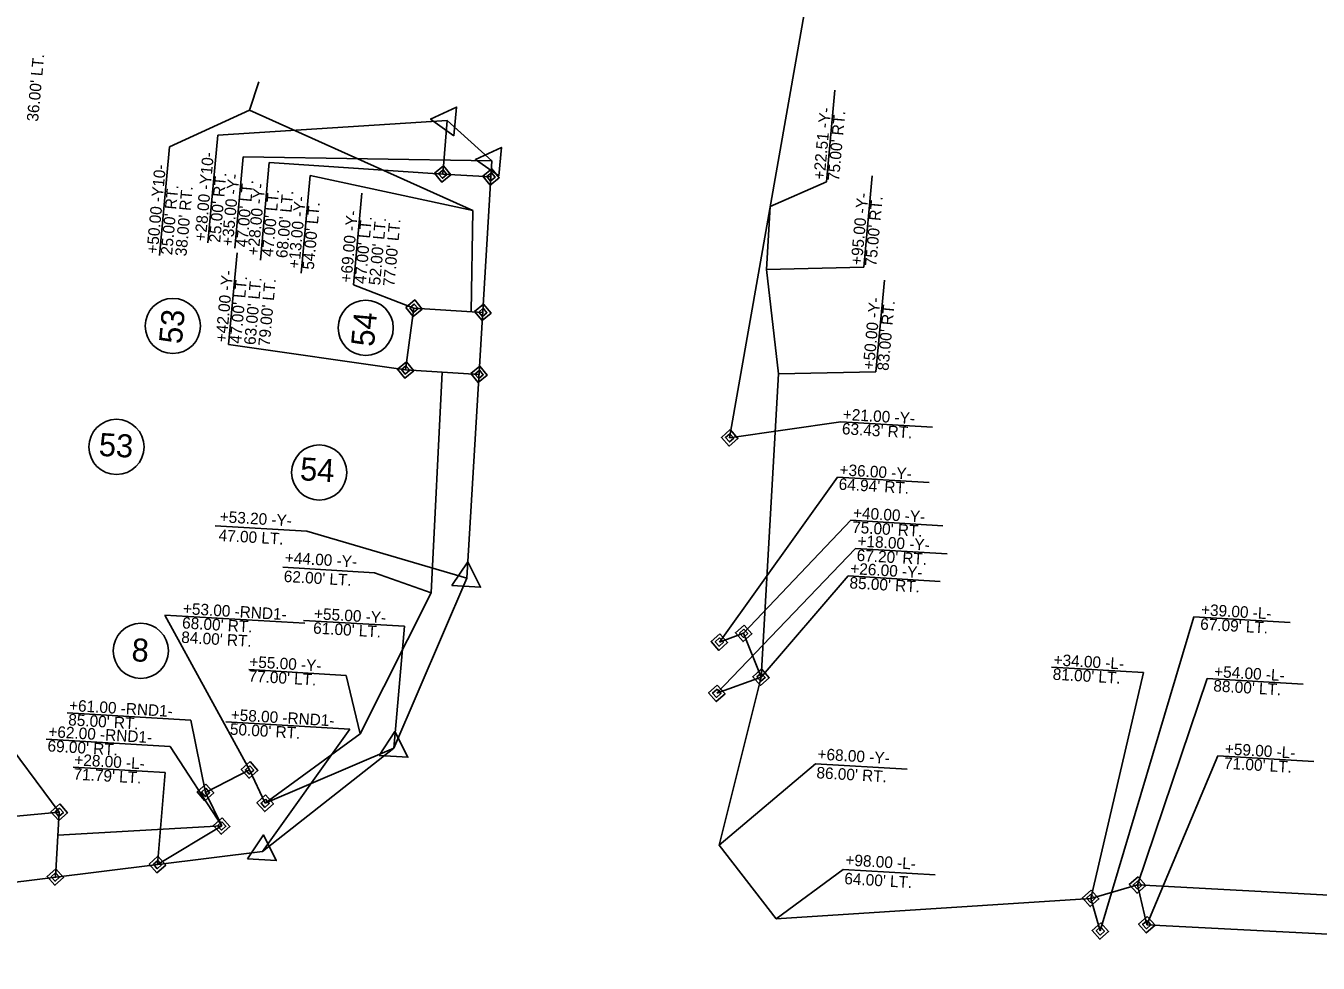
# Model space of a CAD drawing. Extents: x 2010883 to 2014849, y 442000 to 447413.
# Drawn here: x 2011813 to 2012375, y 445024 to 445432 of the extents above; entities that cross this region are included whole.
import ezdxf

# ---------------------------------------------------------------- set-up
doc = ezdxf.new("R2010")
doc.units = 0
for name, color, linetype in [('Prop Easement Construction', 7, 'Continuous'), ('Prop Easement Construction Station Offsets', 7, 'Continuous'), ('Prop Easement Permanent Drainage', 7, 'Continuous'), ('Prop Easement Permanent Drainage Station Offsets', 7, 'Continuous'), ('Prop Easement Permanent Utility', 7, 'Continuous'), ('Prop Easement Permanent Utility Station Offsets', 7, 'Continuous'), ('Prop Parcel Number CELL', 7, 'Continuous'), ('Prop Parcel Number Text', 7, 'Continuous'), ('Prop ROW Marker CELL', 7, 'Continuous'), ('Prop ROW Permanent Easement CELL', 7, 'Continuous'), ('Prop ROW RW Lines', 7, 'Continuous'), ('Prop ROW Station Offsets', 7, 'Continuous')]:
    doc.layers.add(name, color=color, linetype=linetype)

msp = doc.modelspace()

# ---------------------------------------------------------------- linework, layer by layer
at = {"layer": 'Prop Easement Construction'}
for p, q in [((2011910.56, 445395.34), (2011914.63, 445407.68)), ((2012007.68, 445351.78), (2011910.56, 445395.34)), ((2012007.03, 445307.74), (2012007.68, 445351.78)), ((2012135.36, 445326.06), (2012137.01, 445353.51)), ((2012140.64, 445280.66), (2012135.36, 445326.06)), ((2011989.53, 445185.57), (2011994.41, 445281.45)), ((2012133.02, 445148.82), (2012140.64, 445280.66)), ((2011958.68, 445124.25), (2011989.53, 445185.57)), ((2012114.82, 445075.77), (2012133.02, 445148.82)), ((2011917.38, 445094.01), (2011958.68, 445124.25)), ((2011827.22, 445080.12), (2011898.48, 445084.13)), ((2012114.82, 445075.77), (2012139.62, 445043.68)), ((2012296.76, 445058.46), (2012623.31, 445041.21)), ((2012139.62, 445043.68), (2012276.39, 445052.65))]:
    msp.add_line(p, q, dxfattribs=at)
at = {"layer": 'Prop Easement Construction Station Offsets'}
for p, q in [((2012161.48, 445364.18), (2012165.14, 445404.01)), ((2011910.56, 445395.34), (2011875.84, 445379.49)), ((2011871.49, 445332.23), (2011875.84, 445379.49)), ((2011933.03, 445324.52), (2011936.93, 445366.95)), ((2011936.93, 445366.95), (2012007.68, 445351.78)), ((2012177.71, 445327.06), (2012181.37, 445366.89)), ((2012137.01, 445353.51), (2012161.48, 445364.18)), ((2012135.36, 445326.06), (2012177.71, 445327.06)), ((2012182.99, 445281.66), (2012186.65, 445321.49)), ((2012140.64, 445280.66), (2012182.99, 445281.66)), ((2011925, 445196.59), (2011964.94, 445194.23)), ((2011989.53, 445185.57), (2011964.94, 445194.23)), ((2011910.32, 445152.12), (2011952.66, 445149.62)), ((2011958.68, 445124.25), (2011952.66, 445149.62)), ((2012114.82, 445075.77), (2012156.64, 445111.2)), ((2012156.64, 445111.2), (2012196.57, 445108.85)), ((2012139.62, 445043.68), (2012168.77, 445065.18)), ((2012168.77, 445065.18), (2012208.7, 445062.82))]:
    msp.add_line(p, q, dxfattribs=at)
at = {"layer": 'Prop Easement Permanent Drainage'}
for p, q in [((2011994.6, 445367.59), (2011996.46, 445390.81)), ((2012015.56, 445366.33), (2011994.6, 445367.59)), ((2011807.67, 445088.29), (2011827.81, 445090.11)), ((2011826.15, 445061.91), (2011827.81, 445090.11))]:
    msp.add_line(p, q, dxfattribs=at)
at = {"layer": 'Prop Easement Permanent Drainage Station Offsets'}
for p, q in [((2011915.28, 445330.14), (2011919.18, 445372.58)), ((2011919.18, 445372.58), (2011994.6, 445367.59)), ((2011793.66, 445136.03), (2011827.81, 445090.11))]:
    msp.add_line(p, q, dxfattribs=at)
at = {"layer": 'Prop Easement Permanent Utility'}
for p, q in [((2012119.36, 445252.89), (2012162.12, 445496.62)), ((2011978.45, 445282.41), (2011982.07, 445309.24)), ((2011982.07, 445309.24), (2012012.02, 445307.44)), ((2012010.39, 445280.49), (2011978.45, 445282.41)), ((2012125.45, 445167.9), (2012114.88, 445164.09)), ((2012133.02, 445148.82), (2012125.45, 445167.9)), ((2012113.76, 445141.83), (2012133.02, 445148.82)), ((2011917.38, 445094.01), (2011973.39, 445117.95)), ((2011891.43, 445098.71), (2011910.59, 445108.5)), ((2011910.59, 445108.5), (2011917.38, 445094.01)), ((2011898.48, 445084.13), (2011891.43, 445098.71)), ((2011870.55, 445067.34), (2011898.48, 445084.13)), ((2012276.39, 445052.65), (2012296.76, 445058.46)), ((2012296.76, 445058.46), (2012300.75, 445041.19)), ((2012280.56, 445038.46), (2012276.39, 445052.65)), ((2012300.75, 445041.19), (2012618.32, 445024.48))]:
    msp.add_line(p, q, dxfattribs=at)
at = {"layer": 'Prop Easement Permanent Utility Station Offsets'}
for p, q in [((2011955.74, 445319.43), (2011959.4, 445359.26)), ((2011901.5, 445293.47), (2011905.17, 445333.3)), ((2011955.74, 445319.43), (2011982.07, 445309.24)), ((2011901.5, 445293.47), (2011978.45, 445282.41)), ((2012119.36, 445252.89), (2012167.68, 445259.86)), ((2012167.68, 445259.86), (2012207.61, 445257.5)), ((2012114.88, 445164.09), (2012166.26, 445235.76)), ((2012166.26, 445235.76), (2012206.19, 445233.41)), ((2012125.45, 445167.9), (2012172.12, 445217.03)), ((2012172.12, 445217.03), (2012212.06, 445214.68)), ((2012113.76, 445141.83), (2012174.09, 445204.81)), ((2012174.09, 445204.81), (2012214.02, 445202.46)), ((2012133.02, 445148.82), (2012170.96, 445192.84)), ((2012170.96, 445192.84), (2012210.89, 445190.48)), ((2011873.68, 445175.84), (2011934.64, 445172.24)), ((2011910.59, 445108.5), (2011873.68, 445175.84)), ((2012280.56, 445038.46), (2012321.26, 445175.12)), ((2012321.26, 445175.12), (2012363.06, 445172.66)), ((2012259.35, 445153.18), (2012299.28, 445150.83)), ((2012276.39, 445052.65), (2012299.28, 445150.83)), ((2012296.76, 445058.46), (2012326.97, 445148.24)), ((2012326.97, 445148.24), (2012368.77, 445145.78)), ((2011831.21, 445133.29), (2011885.12, 445130.12)), ((2011891.43, 445098.71), (2011885.12, 445130.12)), ((2011822.21, 445121.93), (2011876.12, 445118.75)), ((2011898.48, 445084.13), (2011876.12, 445118.75)), ((2012300.75, 445041.19), (2012331.62, 445114.6)), ((2012331.62, 445114.6), (2012373.42, 445112.13)), ((2011833.91, 445109.71), (2011873.84, 445107.36)), ((2011870.55, 445067.34), (2011873.84, 445107.36))]:
    msp.add_line(p, q, dxfattribs=at)
at = {"layer": 'Prop Parcel Number CELL'}
for p, q in [((2011877.23, 445301.55), (2011877.23, 445301.55)), ((2011961.1, 445300.73), (2011961.1, 445300.73)), ((2011852.71, 445248.95), (2011852.71, 445248.95)), ((2011940.89, 445237.82), (2011940.89, 445237.82)), ((2011863.3, 445160.26), (2011863.3, 445160.26))]:
    msp.add_line(p, q, dxfattribs=at)
for centre in [(2011877.23, 445301.55), (2011961.1, 445300.73), (2011852.71, 445248.95), (2011940.89, 445237.82), (2011863.3, 445160.26)]:
    msp.add_circle(centre, 12, dxfattribs=at)
at = {"layer": 'Prop ROW Marker CELL'}
for p, q in [((2011996.46, 445390.81), (2011996.46, 445390.81)), ((2012015.99, 445373.32), (2012015.99, 445373.32)), ((2011994.6, 445367.59), (2011994.6, 445367.59)), ((2012015.56, 445366.33), (2012015.56, 445366.33)), ((2011982.07, 445309.24), (2011982.07, 445309.24)), ((2012012.02, 445307.44), (2012012.02, 445307.44)), ((2011978.45, 445282.41), (2011978.45, 445282.41)), ((2012010.39, 445280.49), (2012010.39, 445280.49)), ((2012119.36, 445252.89), (2012119.36, 445252.89)), ((2012005.06, 445191.85), (2012005.06, 445191.85)), ((2012114.88, 445164.09), (2012114.88, 445164.09)), ((2012125.45, 445167.9), (2012125.45, 445167.9)), ((2012133.02, 445148.82), (2012133.02, 445148.82)), ((2012113.76, 445141.83), (2012113.76, 445141.83)), ((2011973.39, 445117.95), (2011973.39, 445117.95)), ((2011910.59, 445108.5), (2011910.59, 445108.5)), ((2011891.43, 445098.71), (2011891.43, 445098.71)), ((2011917.38, 445094.01), (2011917.38, 445094.01)), ((2011827.81, 445090.11), (2011827.81, 445090.11)), ((2011898.48, 445084.13), (2011898.48, 445084.13)), ((2011916.2, 445073.02), (2011916.2, 445073.02)), ((2011870.55, 445067.34), (2011870.55, 445067.34)), ((2011826.15, 445061.91), (2011826.15, 445061.91)), ((2012296.76, 445058.46), (2012296.76, 445058.46)), ((2012276.39, 445052.65), (2012276.39, 445052.65)), ((2012300.75, 445041.19), (2012300.75, 445041.19)), ((2012280.56, 445038.46), (2012280.56, 445038.46))]:
    msp.add_line(p, q, dxfattribs=at)
for points in [[(2011999.48, 445384.25), (2011989.29, 445391.47), (2012000.62, 445396.7)], [(2012019, 445366.77), (2012008.82, 445373.98), (2012020.14, 445379.21)], [(2011998.6, 445188.62), (2012005.48, 445199.04), (2012011.08, 445187.89)], [(2011966.94, 445114.73), (2011973.81, 445125.14), (2011979.42, 445113.99)], [(2011909.74, 445069.79), (2011916.62, 445080.21), (2011922.22, 445069.06)]]:
    msp.add_lwpolyline(points, close=True, dxfattribs=at)
at = {"layer": 'Prop ROW Permanent Easement CELL'}
for points in [[(2011991.02, 445367.92), (2011994.93, 445371.18), (2011998.19, 445367.26), (2011994.27, 445364.01)], [(2011992.81, 445367.76), (2011994.77, 445369.39), (2011996.39, 445367.43), (2011994.44, 445365.8)], [(2012011.98, 445366.66), (2012015.89, 445369.92), (2012019.15, 445366), (2012015.24, 445362.75)], [(2012013.77, 445366.5), (2012015.73, 445368.12), (2012017.36, 445366.17), (2012015.4, 445364.54)], [(2011978.49, 445309.57), (2011982.4, 445312.83), (2011985.66, 445308.91), (2011981.74, 445305.66)], [(2011980.28, 445309.41), (2011982.24, 445311.03), (2011983.86, 445309.08), (2011981.91, 445307.45)], [(2012008.43, 445307.77), (2012012.35, 445311.02), (2012015.6, 445307.11), (2012011.69, 445303.85)], [(2012010.23, 445307.6), (2012012.18, 445309.23), (2012013.81, 445307.27), (2012011.85, 445305.65)], [(2011974.87, 445282.74), (2011978.78, 445286), (2011982.04, 445282.08), (2011978.12, 445278.83)], [(2011976.66, 445282.58), (2011978.62, 445284.2), (2011980.24, 445282.25), (2011978.29, 445280.62)], [(2012006.81, 445280.82), (2012010.72, 445284.07), (2012013.98, 445280.16), (2012010.07, 445276.9)], [(2012008.6, 445280.65), (2012010.56, 445282.28), (2012012.19, 445280.32), (2012010.23, 445278.69)], [(2012119.57, 445256.48), (2012122.95, 445252.67), (2012119.15, 445249.29), (2012115.77, 445253.1)], [(2012119.47, 445254.68), (2012121.16, 445252.78), (2012119.25, 445251.09), (2012117.56, 445252.99)], [(2012125.66, 445171.49), (2012129.04, 445167.69), (2012125.24, 445164.3), (2012121.85, 445168.11)], [(2012125.55, 445169.69), (2012127.24, 445167.79), (2012125.34, 445166.1), (2012123.65, 445168)], [(2012115.1, 445167.68), (2012118.48, 445163.88), (2012114.67, 445160.49), (2012111.29, 445164.3)], [(2012114.99, 445165.88), (2012116.68, 445163.98), (2012114.78, 445162.29), (2012113.09, 445164.19)], [(2012133.23, 445152.41), (2012136.61, 445148.6), (2012132.8, 445145.22), (2012129.42, 445149.03)], [(2012133.12, 445150.61), (2012134.81, 445148.71), (2012132.91, 445147.02), (2012131.22, 445148.92)], [(2012113.97, 445145.42), (2012117.36, 445141.62), (2012113.55, 445138.24), (2012110.17, 445142.04)], [(2012113.87, 445143.63), (2012115.56, 445141.73), (2012113.66, 445140.03), (2012111.97, 445141.94)], [(2011910.8, 445112.09), (2011914.19, 445108.28), (2011910.38, 445104.9), (2011907, 445108.71)], [(2011910.7, 445110.29), (2011912.39, 445108.39), (2011910.49, 445106.7), (2011908.8, 445108.6)], [(2011891.64, 445102.3), (2011895.02, 445098.5), (2011891.21, 445095.12), (2011887.83, 445098.92)], [(2011891.53, 445100.51), (2011893.22, 445098.6), (2011891.32, 445096.91), (2011889.63, 445098.82)], [(2011917.59, 445097.6), (2011920.98, 445093.8), (2011917.17, 445090.41), (2011913.79, 445094.22)], [(2011828.03, 445093.7), (2011831.41, 445089.9), (2011827.6, 445086.51), (2011824.22, 445090.32)], [(2011827.92, 445091.9), (2011829.61, 445090), (2011827.71, 445088.31), (2011826.02, 445090.21)], [(2011917.49, 445095.8), (2011919.18, 445093.9), (2011917.28, 445092.21), (2011915.59, 445094.11)], [(2011898.7, 445087.72), (2011902.08, 445083.92), (2011898.27, 445080.54), (2011894.89, 445084.34)], [(2011898.59, 445085.93), (2011900.28, 445084.02), (2011898.38, 445082.33), (2011896.69, 445084.24)], [(2011870.76, 445070.94), (2011874.14, 445067.13), (2011870.34, 445063.75), (2011866.95, 445067.55)], [(2011870.65, 445069.14), (2011872.34, 445067.24), (2011870.44, 445065.55), (2011868.75, 445067.45)], [(2011826.36, 445065.51), (2011829.75, 445061.7), (2011825.94, 445058.32), (2011822.56, 445062.13)], [(2011826.26, 445063.71), (2011827.95, 445061.81), (2011826.05, 445060.12), (2011824.35, 445062.02)], [(2012296.98, 445062.05), (2012300.36, 445058.24), (2012296.55, 445054.86), (2012293.17, 445058.67)], [(2012296.87, 445060.25), (2012298.56, 445058.35), (2012296.66, 445056.66), (2012294.97, 445058.56)], [(2012276.6, 445056.24), (2012279.98, 445052.43), (2012276.17, 445049.05), (2012272.79, 445052.86)], [(2012276.49, 445054.44), (2012278.18, 445052.54), (2012276.28, 445050.85), (2012274.59, 445052.75)], [(2012280.77, 445042.06), (2012284.15, 445038.25), (2012280.35, 445034.87), (2012276.96, 445038.67)], [(2012300.97, 445044.79), (2012304.35, 445040.98), (2012300.54, 445037.6), (2012297.16, 445041.4)], [(2012300.86, 445042.99), (2012302.55, 445041.09), (2012300.65, 445039.4), (2012298.96, 445041.3)], [(2012280.66, 445040.26), (2012282.36, 445038.36), (2012280.45, 445036.67), (2012278.76, 445038.57)]]:
    msp.add_lwpolyline(points, close=True, dxfattribs=at)
at = {"layer": 'Prop ROW RW Lines'}
for p, q in [((2012015.99, 445373.32), (2011996.46, 445390.81)), ((2012005.06, 445191.85), (2012015.99, 445373.32)), ((2011973.39, 445117.95), (2012005.06, 445191.85)), ((2011916.2, 445073.02), (2011973.39, 445117.95)), ((2011751.47, 445052.53), (2011916.2, 445073.02))]:
    msp.add_line(p, q, dxfattribs=at)
at = {"layer": 'Prop ROW Station Offsets'}
for p, q in [((2011896.74, 445384.47), (2011996.46, 445390.81)), ((2011892.44, 445337.67), (2011896.74, 445384.47)), ((2011904.21, 445335.31), (2011907.87, 445375.14)), ((2011907.87, 445375.14), (2012015.99, 445373.32)), ((2011895.57, 445214.59), (2011935.5, 445212.24)), ((2012005.06, 445191.85), (2011935.5, 445212.24)), ((2011934.02, 445173.54), (2011977.95, 445170.95)), ((2011973.39, 445117.95), (2011977.95, 445170.95)), ((2011900.27, 445129.45), (2011954.18, 445126.27)), ((2011916.2, 445073.02), (2011954.18, 445126.27))]:
    msp.add_line(p, q, dxfattribs=at)

# ---------------------------------------------------------------- texts
at = {"layer": 'Prop Easement Construction Station Offsets'}
for s, rotation, p in [("36.00' LT.", 84.7467, (2011818.64, 445390.24)), ('+22.51 -Y-', 84.7467, (2012160.66, 445364.98)), ("75.00' RT.", 84.7467, (2012166.89, 445364.41)), ('+50.00 -Y10-', 84.7467, (2011870.68, 445332.81)), ("25.00' RT.", 84.7467, (2011876.9, 445332.23)), ("38.00' RT.", 84.7467, (2011883.13, 445331.66)), ('+13.00 -Y-', 84.7467, (2011932.28, 445326.41)), ('+95.00 -Y-', 84.7467, (2012176.89, 445327.86)), ("75.00' RT.", 84.7467, (2012183.12, 445327.29)), ("54.00' LT.", 84.7467, (2011938.5, 445325.84)), ('+50.00 -Y-', 84.7467, (2012182.17, 445282.47)), ("83.00' RT.", 84.7467, (2012188.4, 445281.89)), ('+44.00 -Y-', 356.6264, (2011925.84, 445198.37)), ("62.00' LT.", 356.6264, (2011925.36, 445190.26)), ('+55.00 -Y-', 356.6264, (2011910.38, 445153.15)), ("77.00' LT.", 356.6264, (2011910.01, 445146.91)), ('+68.00 -Y-', 356.6264, (2012157.47, 445112.99)), ("86.00' RT.", 356.6264, (2012157, 445104.88)), ('+98.00 -L-', 356.6264, (2012169.6, 445066.96)), ("64.00' LT.", 356.6264, (2012169.13, 445058.85))]:
    msp.add_text(s, height=5, rotation=rotation, dxfattribs=at).set_placement(p)
at = {"layer": 'Prop Easement Permanent Drainage Station Offsets'}
for s, p in [('+28.00 -Y-', (2011914.53, 445332.03)), ("47.00' LT.", (2011920.76, 445331.46)), ("68.00' LT.", (2011926.98, 445330.89))]:
    msp.add_text(s, height=5, rotation=84.7467, dxfattribs=at).set_placement(p)
at = {"layer": 'Prop Easement Permanent Utility Station Offsets'}
for s, rotation, p in [('+69.00 -Y-', 84.7467, (2011954.9, 445320.24)), ("47.00' LT.", 84.7467, (2011961.12, 445319.67)), ("52.00' LT.", 84.7467, (2011967.34, 445319.09)), ("77.00' LT.", 84.7467, (2011973.57, 445318.52)), ('+42.00 -Y-', 84.7467, (2011900.66, 445294.27)), ("47.00' LT.", 84.7467, (2011906.88, 445293.7)), ("63.00' LT.", 84.7467, (2011913.11, 445293.13)), ("79.00' LT.", 84.7467, (2011919.33, 445292.56)), ('+21.00 -Y-', 356.6264, (2012168.46, 445260.7)), ("63.43' RT.", 356.6264, (2012168.09, 445254.46)), ('+36.00 -Y-', 356.6264, (2012167.04, 445236.6)), ("64.94' RT.", 356.6264, (2012166.67, 445230.36)), ('+40.00 -Y-', 356.6264, (2012172.9, 445217.87)), ("75.00' RT.", 356.6264, (2012172.53, 445211.63)), ('+18.00 -Y-', 356.6264, (2012174.87, 445205.65)), ("67.20' RT.", 356.6264, (2012174.5, 445199.41)), ('+26.00 -Y-', 356.6264, (2012171.73, 445193.68)), ("85.00' RT.", 356.6264, (2012171.36, 445187.44)), ('+53.00 -RND1-', 356.6264, (2011881.51, 445176.27)), ('+39.00 -L-', 356.6264, (2012324.25, 445175.77)), ("68.00' RT.", 356.6264, (2011881.15, 445170.03)), ("67.09' LT.", 356.6264, (2012323.88, 445169.53)), ("84.00' RT.", 356.6264, (2011880.78, 445163.79)), ('+34.00 -L-', 356.6264, (2012260.12, 445153.96)), ('+54.00 -L-', 356.6264, (2012329.96, 445148.89)), ("81.00' LT.", 356.6264, (2012259.75, 445147.72)), ("88.00' LT.", 356.6264, (2012329.59, 445142.65)), ('+61.00 -RND1-', 356.6264, (2011831.99, 445134.15)), ("85.00' RT.", 356.6264, (2011831.62, 445127.91)), ('+62.00 -RND1-', 356.6264, (2011822.99, 445122.78)), ("69.00' RT.", 356.6264, (2011822.62, 445116.55)), ('+59.00 -L-', 356.6264, (2012334.61, 445115.25)), ('+28.00 -L-', 356.6264, (2011834.28, 445110.53)), ("71.00' LT.", 356.6264, (2012334.24, 445109.01)), ("71.79' LT.", 356.6264, (2011833.92, 445104.29))]:
    msp.add_text(s, height=5, rotation=rotation, dxfattribs=at).set_placement(p)
at = {"layer": 'Prop Parcel Number Text'}
for s, rotation, p in [('53', 84.7467, (2011881.11, 445293.46)), ('54', 84.7467, (2011964.65, 445292.28)), ('53', 356.6264, (2011844.85, 445245.09)), ('54', 356.6264, (2011932.36, 445234.48)), ('8', 356.6264, (2011859.08, 445155.82))]:
    msp.add_text(s, height=10, rotation=rotation, dxfattribs=at).set_placement(p)
at = {"layer": 'Prop ROW Station Offsets'}
for s, rotation, p in [('+28.00 -Y10-', 84.7467, (2011891.56, 445338.2)), ("25.00' RT.", 84.7467, (2011897.79, 445337.63)), ('+35.00 -Y-', 84.7467, (2011903.36, 445336.12)), ("47.00' LT.", 84.7467, (2011909.59, 445335.55)), ('+53.20 -Y-', 356.6264, (2011897.51, 445216.22)), ('47.00 LT.', 356.6264, (2011897.03, 445208.1)), ('+55.00 -Y-', 356.6264, (2011938.5, 445174.05)), ("61.00' LT.", 356.6264, (2011938.13, 445167.81)), ('+58.00 -RND1-', 356.6264, (2011902.3, 445130.08)), ("50.00' RT.", 356.6264, (2011901.93, 445123.84))]:
    msp.add_text(s, height=5, rotation=rotation, dxfattribs=at).set_placement(p)

doc.saveas('drawing.dxf')
